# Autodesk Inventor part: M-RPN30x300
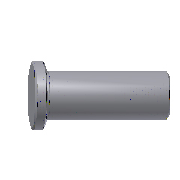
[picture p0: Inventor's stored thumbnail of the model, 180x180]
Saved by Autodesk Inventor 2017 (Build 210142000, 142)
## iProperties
Created: 2016-02
Part Number: M-RPN30x300
Material: SUJ 2
Description: Return Pin
Document SubType Name: Modeling
Designer: Sandeep
Standard Revision: 1
Manufacturer: FUTABA
Language: en-US
Size Designation: 30x300
Categories: <MemberInstance><Categories><Category DisplayName="Mold" InternalName="349578f2-f4d4-4954-8c09-8e99297a61c0" Mnemonic="MOLD"><Category DisplayName="Return Compo
Mass: 6.63789 g
Surface Area: 25.7048 cm^2
Volume: 6.63789 cm^3
Density: 7.85 g/cm^3
Appearance: Aluminum - Dark
IsCustomPart: 1
Author: Sandeep
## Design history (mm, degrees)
body "Solid1"
revolve "Revolution1" stored, may be unused: angle "d41" = 90 deg
revolve "Revolution2" stored, may be unused: angle "d48" = 90 deg
chamfer "Chamfer1" distance "d49" = 0.5; stored, may be unused: second distance "d50" = 2, angle "d51" = 45 deg
sketch "Sketch1"
  geometry: L1 (0, -15)-(0, 62) reference; L2 (0, -4)-(17.5, -4); L3 (17.5, -4)-(17.5, 0); L4 (17.5, 0)-(15, 0); L5 (15, 0)-(15, 296); L6 (15, 296)-(0, 296); L7 (0, 296)-(0, -4); 1 further point
  constraints: 12 end point, 3 perpendicular, 2 parallel, 2 point on line, 1 collinear, 1 horizontal alignment
  dimensions: "d28" = 4 distance between parallel lines of L2 L4 (= H_); "d29" = 35 diameter of L3 L1 (= D); "d31" = 30 diameter of L5 L1 (= d_); "d33" = 300 distance between parallel lines of L2 L6 (= L)
sketch "Sketch2" dims "d28" = 4 (= H_), "d29" = 35 (= D), "d31" = 30 (= d_), "d33" = 300 (= L)
  geometry: L1 (15, 296)-(15, 0) reference; L2 (-15, 0)-(15, 0) reference; L3 (15, 0)-(14.8, 0); L4 (14.5, 0.3)-(14.5, 0.9); L5 (14.8, 1.2)-(15, 1.2); L6 (15, 1.2)-(15, 0); L7 (0, -10.275)-(0, 61.212) reference; A1 r 0.3 centre (14.8, 0.9) between (14.8, 1.2) and (14.5, 0.9); A2 r 0.3 centre (14.8, 0.3) between (14.5, 0.3) and (14.8, 0); 1 further point
  constraints: 8 end point, 4 point on circle, 4 tangent, 2 centre point, 2 parallel, 1 equal radius, 1 horizontal, 1 perpendicular
  dimensions: "d45" = 0.3 radius of A1; "d46" = 1.2 distance between parallel lines of L2 L5; "d47" = 0.5 distance between parallel lines of L4 L1
other parameters: "d_" = 30 [user parameter; used in 1 equation term], "L" = 300 [user parameter; used in 1 equation term], "D" = 35 [user parameter; used in 1 equation term], "H_" = 4 [user parameter; used in 1 equation term], "d44" = 0, "d52" = 0, "d53" = 0
